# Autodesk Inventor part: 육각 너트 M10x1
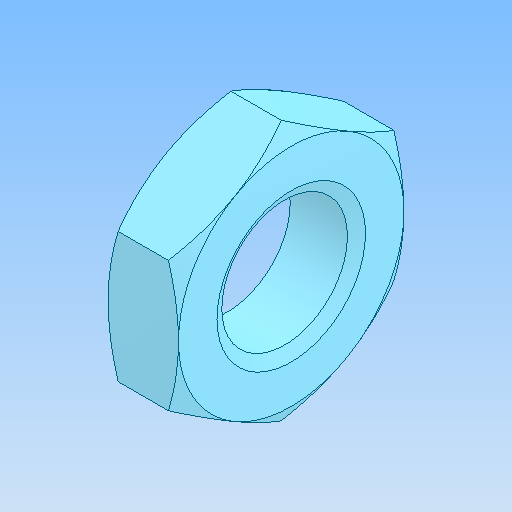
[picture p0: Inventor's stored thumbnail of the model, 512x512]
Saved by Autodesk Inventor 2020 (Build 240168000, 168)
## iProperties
Created: 2024-09
Part Number: 육각 너트 M10x1
Material: 강철, 연강
Description: 6각 너트 및 6각 가는 너트 - 이중 모따기
Document SubType Name: Modeling
Designer: oem
Density: 7.85 g/cm^3
Appearance: 기본값
Author: jhkim
Sending System: Autodesk Inventor 2025
Preprocessor: ST-DEVELOPER v20
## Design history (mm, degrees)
feature "Solid1"
node "솔리드1"
